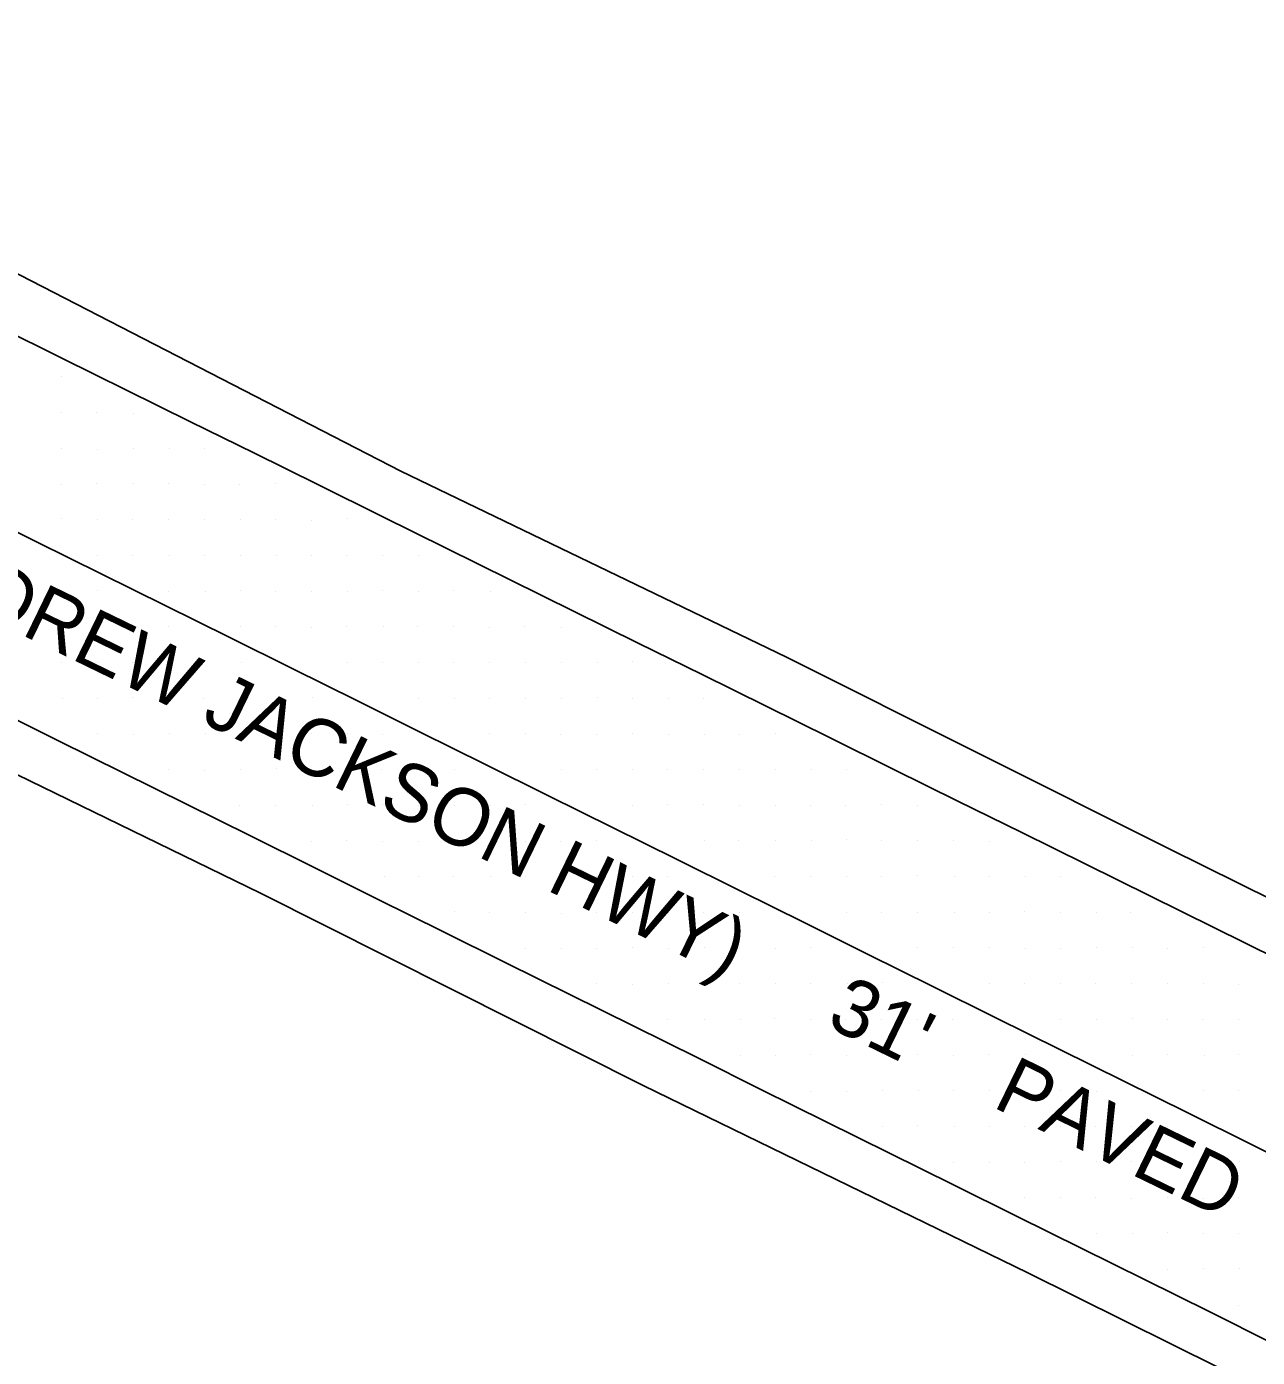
# Model space of a CAD drawing. Extents: x 2244337 to 2251208, y 199469 to 202984.
# Drawn here: x 2244431.6 to 2244517.9, y 202861.5 to 202954.8 of the extents above; entities that cross this region are included whole.
import ezdxf

# ---------------------------------------------------------------- set-up
doc = ezdxf.new("R2010")
doc.units = 0
for name, color, linetype in [('Exist DTM Scan Elevation Point', 7, 'Continuous'), ('Exist Roads EOP', 7, 'Continuous'), ('Exist Roads EOT', 7, 'Continuous'), ('Exist Roads Text', 7, 'Continuous')]:
    doc.layers.add(name, color=color, linetype=linetype)

msp = doc.modelspace()

# ---------------------------------------------------------------- linework, layer by layer
at = {"layer": 'Exist DTM Scan Elevation Point'}
for p, q in [((2244434.067, 202930.21), (2244434.067, 202930.21)), ((2244434.073, 202927.707), (2244434.073, 202927.707)), ((2244436.537, 202927.747), (2244436.537, 202927.747)), ((2244439.096, 202927.674), (2244439.096, 202927.674)), ((2244434.076, 202925.195), (2244434.076, 202925.195)), ((2244436.591, 202925.154), (2244436.591, 202925.154)), ((2244439.102, 202925.209), (2244439.102, 202925.209)), ((2244441.592, 202925.189), (2244441.592, 202925.189)), ((2244444.103, 202925.219), (2244444.103, 202925.219)), ((2244434.046, 202922.709), (2244434.046, 202922.709)), ((2244436.522, 202922.734), (2244436.522, 202922.734)), ((2244439.092, 202922.714), (2244439.092, 202922.714)), ((2244441.565, 202922.742), (2244441.565, 202922.742)), ((2244449.079, 202922.718), (2244449.079, 202922.718)), ((2244444.102, 202922.683), (2244444.102, 202922.683)), ((2244446.562, 202922.65), (2244446.562, 202922.65)), ((2244434.087, 202920.262), (2244434.087, 202920.262)), ((2244436.59, 202920.211), (2244436.59, 202920.211)), ((2244439.049, 202920.203), (2244439.049, 202920.203)), ((2244441.558, 202920.226), (2244441.558, 202920.226)), ((2244444.089, 202920.198), (2244444.089, 202920.198)), ((2244446.621, 202920.205), (2244446.621, 202920.205)), ((2244449.08, 202920.221), (2244449.08, 202920.221)), ((2244451.584, 202920.187), (2244451.584, 202920.187)), ((2244454.078, 202920.262), (2244454.078, 202920.262)), ((2244436.578, 202917.711), (2244436.578, 202917.711)), ((2244439.065, 202917.689), (2244439.065, 202917.689)), ((2244441.6, 202917.712), (2244441.6, 202917.712)), ((2244444.083, 202917.71), (2244444.083, 202917.71)), ((2244446.567, 202917.73), (2244446.567, 202917.73)), ((2244449.127, 202917.714), (2244449.127, 202917.714)), ((2244451.601, 202917.705), (2244451.601, 202917.705)), ((2244454.058, 202917.686), (2244454.058, 202917.686)), ((2244456.564, 202917.669), (2244456.564, 202917.669)), ((2244459.069, 202917.678), (2244459.069, 202917.678)), ((2244446.589, 202915.251), (2244446.589, 202915.251)), ((2244456.571, 202915.24), (2244456.571, 202915.24)), ((2244461.544, 202915.239), (2244461.544, 202915.239)), ((2244431.616, 202915.211), (2244431.616, 202915.211)), ((2244434.1, 202915.221), (2244434.1, 202915.221)), ((2244436.568, 202915.227), (2244436.568, 202915.227)), ((2244441.57, 202915.212), (2244441.57, 202915.212)), ((2244444.114, 202915.195), (2244444.114, 202915.195)), ((2244449.067, 202915.169), (2244449.067, 202915.169)), ((2244451.611, 202915.21), (2244451.611, 202915.21)), ((2244454.108, 202915.187), (2244454.108, 202915.187)), ((2244459.054, 202915.195), (2244459.054, 202915.195)), ((2244464.095, 202915.21), (2244464.095, 202915.21)), ((2244434.13, 202912.716), (2244434.13, 202912.716)), ((2244436.572, 202912.749), (2244436.572, 202912.749)), ((2244439.017, 202912.757), (2244439.017, 202912.757)), ((2244441.578, 202912.747), (2244441.578, 202912.747)), ((2244446.585, 202912.714), (2244446.585, 202912.714)), ((2244449.072, 202912.701), (2244449.072, 202912.701)), ((2244451.575, 202912.664), (2244451.575, 202912.664)), ((2244454.059, 202912.72), (2244454.059, 202912.72)), ((2244456.596, 202912.7), (2244456.596, 202912.7)), ((2244459.035, 202912.76), (2244459.035, 202912.76)), ((2244461.563, 202912.745), (2244461.563, 202912.745)), ((2244464.063, 202912.686), (2244464.063, 202912.686)), ((2244466.532, 202912.713), (2244466.532, 202912.713)), ((2244469.084, 202912.685), (2244469.084, 202912.685)), ((2244434.088, 202910.189), (2244434.088, 202910.189)), ((2244436.58, 202910.226), (2244436.58, 202910.226)), ((2244439.043, 202910.195), (2244439.043, 202910.195)), ((2244441.571, 202910.17), (2244441.571, 202910.17)), ((2244444.039, 202910.231), (2244444.039, 202910.231)), ((2244446.648, 202910.216), (2244446.648, 202910.216)), ((2244454.076, 202910.206), (2244454.076, 202910.206)), ((2244456.57, 202910.231), (2244456.57, 202910.231)), ((2244459.075, 202910.223), (2244459.075, 202910.223)), ((2244461.562, 202910.191), (2244461.562, 202910.191)), ((2244464.068, 202910.207), (2244464.068, 202910.207)), ((2244466.582, 202910.234), (2244466.582, 202910.234)), ((2244469.11, 202910.212), (2244469.11, 202910.212)), ((2244471.593, 202910.221), (2244471.593, 202910.221)), ((2244474.091, 202910.248), (2244474.091, 202910.248)), ((2244434.1, 202907.679), (2244434.1, 202907.679)), ((2244436.576, 202907.719), (2244436.576, 202907.719)), ((2244439.053, 202907.726), (2244439.053, 202907.726)), ((2244441.579, 202907.724), (2244441.579, 202907.724)), ((2244444.012, 202907.712), (2244444.012, 202907.712)), ((2244446.565, 202907.706), (2244446.565, 202907.706)), ((2244449.128, 202907.718), (2244449.128, 202907.718)), ((2244451.622, 202907.74), (2244451.622, 202907.74)), ((2244459.077, 202907.689), (2244459.077, 202907.689)), ((2244461.596, 202907.697), (2244461.596, 202907.697)), ((2244464.069, 202907.697), (2244464.069, 202907.697)), ((2244466.553, 202907.692), (2244466.553, 202907.692)), ((2244469.113, 202907.679), (2244469.113, 202907.679)), ((2244471.598, 202907.726), (2244471.598, 202907.726)), ((2244474.049, 202907.701), (2244474.049, 202907.701)), ((2244476.564, 202907.704), (2244476.564, 202907.704)), ((2244479.053, 202907.695), (2244479.053, 202907.695)), ((2244436.612, 202905.21), (2244436.612, 202905.21)), ((2244439.09, 202905.175), (2244439.09, 202905.175)), ((2244441.592, 202905.231), (2244441.592, 202905.231)), ((2244444.136, 202905.26), (2244444.136, 202905.26)), ((2244446.541, 202905.217), (2244446.541, 202905.217)), ((2244449.067, 202905.185), (2244449.067, 202905.185)), ((2244451.571, 202905.243), (2244451.571, 202905.243)), ((2244454.08, 202905.206), (2244454.08, 202905.206)), ((2244456.531, 202905.197), (2244456.531, 202905.197)), ((2244464.069, 202905.23), (2244464.069, 202905.23)), ((2244466.577, 202905.22), (2244466.577, 202905.22)), ((2244469.062, 202905.191), (2244469.062, 202905.191)), ((2244471.55, 202905.182), (2244471.55, 202905.182)), ((2244474.07, 202905.213), (2244474.07, 202905.213)), ((2244476.576, 202905.184), (2244476.576, 202905.184)), ((2244479.1, 202905.156), (2244479.1, 202905.156)), ((2244481.565, 202905.187), (2244481.565, 202905.187)), ((2244484.063, 202905.207), (2244484.063, 202905.207)), ((2244441.562, 202902.712), (2244441.562, 202902.712)), ((2244444.093, 202902.673), (2244444.093, 202902.673)), ((2244446.581, 202902.705), (2244446.581, 202902.705)), ((2244449.089, 202902.748), (2244449.089, 202902.748)), ((2244451.603, 202902.679), (2244451.603, 202902.679)), ((2244454.04, 202902.714), (2244454.04, 202902.714)), ((2244456.493, 202902.736), (2244456.493, 202902.736)), ((2244459.076, 202902.712), (2244459.076, 202902.712)), ((2244461.592, 202902.706), (2244461.592, 202902.706)), ((2244469.111, 202902.706), (2244469.111, 202902.706)), ((2244471.566, 202902.685), (2244471.566, 202902.685)), ((2244474.085, 202902.7), (2244474.085, 202902.7)), ((2244476.552, 202902.713), (2244476.552, 202902.713)), ((2244479.051, 202902.703), (2244479.051, 202902.703)), ((2244481.595, 202902.703), (2244481.595, 202902.703)), ((2244484.092, 202902.688), (2244484.092, 202902.688)), ((2244486.599, 202902.69), (2244486.599, 202902.69)), ((2244489.09, 202902.689), (2244489.09, 202902.689)), ((2244446.556, 202900.193), (2244446.556, 202900.193)), ((2244449.047, 202900.196), (2244449.047, 202900.196)), ((2244451.626, 202900.198), (2244451.626, 202900.198)), ((2244454.088, 202900.283), (2244454.088, 202900.283)), ((2244456.57, 202900.242), (2244456.57, 202900.242)), ((2244459.05, 202900.207), (2244459.05, 202900.207)), ((2244461.593, 202900.208), (2244461.593, 202900.208)), ((2244464.115, 202900.192), (2244464.115, 202900.192)), ((2244466.587, 202900.251), (2244466.587, 202900.251)), ((2244474.06, 202900.218), (2244474.06, 202900.218)), ((2244476.56, 202900.262), (2244476.56, 202900.262)), ((2244479.051, 202900.246), (2244479.051, 202900.246)), ((2244481.588, 202900.181), (2244481.588, 202900.181)), ((2244484.085, 202900.194), (2244484.085, 202900.194)), ((2244486.552, 202900.2), (2244486.552, 202900.2)), ((2244489.024, 202900.212), (2244489.024, 202900.212)), ((2244491.502, 202900.261), (2244491.502, 202900.261)), ((2244494.056, 202900.212), (2244494.056, 202900.212)), ((2244451.555, 202897.69), (2244451.555, 202897.69)), ((2244454.048, 202897.736), (2244454.048, 202897.736)), ((2244456.567, 202897.682), (2244456.567, 202897.682)), ((2244459.047, 202897.699), (2244459.047, 202897.699)), ((2244461.56, 202897.706), (2244461.56, 202897.706)), ((2244464.134, 202897.714), (2244464.134, 202897.714)), ((2244466.588, 202897.674), (2244466.588, 202897.674)), ((2244469.057, 202897.695), (2244469.057, 202897.695)), ((2244471.544, 202897.735), (2244471.544, 202897.735)), ((2244479.096, 202897.725), (2244479.096, 202897.725)), ((2244481.532, 202897.711), (2244481.532, 202897.711)), ((2244484.12, 202897.731), (2244484.12, 202897.731)), ((2244486.608, 202897.73), (2244486.608, 202897.73)), ((2244489.058, 202897.774), (2244489.058, 202897.774)), ((2244491.529, 202897.72), (2244491.529, 202897.72)), ((2244494.057, 202897.734), (2244494.057, 202897.734)), ((2244496.54, 202897.725), (2244496.54, 202897.725)), ((2244499.125, 202897.694), (2244499.125, 202897.694)), ((2244456.679, 202895.194), (2244456.679, 202895.194)), ((2244459.058, 202895.198), (2244459.058, 202895.198)), ((2244461.53, 202895.21), (2244461.53, 202895.21)), ((2244464.113, 202895.241), (2244464.113, 202895.241)), ((2244466.577, 202895.219), (2244466.577, 202895.219)), ((2244469.016, 202895.206), (2244469.016, 202895.206)), ((2244471.586, 202895.194), (2244471.586, 202895.194)), ((2244474.081, 202895.21), (2244474.081, 202895.21)), ((2244476.545, 202895.182), (2244476.545, 202895.182)), ((2244484.049, 202895.227), (2244484.049, 202895.227)), ((2244486.581, 202895.231), (2244486.581, 202895.231)), ((2244489.098, 202895.235), (2244489.098, 202895.235)), ((2244491.514, 202895.199), (2244491.514, 202895.199)), ((2244494.069, 202895.265), (2244494.069, 202895.265)), ((2244496.615, 202895.225), (2244496.615, 202895.225)), ((2244499.099, 202895.182), (2244499.099, 202895.182)), ((2244501.619, 202895.21), (2244501.619, 202895.21)), ((2244504.038, 202895.191), (2244504.038, 202895.191)), ((2244461.569, 202892.751), (2244461.569, 202892.751)), ((2244464.082, 202892.682), (2244464.082, 202892.682)), ((2244466.573, 202892.719), (2244466.573, 202892.719)), ((2244469.098, 202892.641), (2244469.098, 202892.641)), ((2244471.576, 202892.659), (2244471.576, 202892.659)), ((2244474.07, 202892.689), (2244474.07, 202892.689)), ((2244476.589, 202892.714), (2244476.589, 202892.714)), ((2244479.047, 202892.714), (2244479.047, 202892.714)), ((2244481.588, 202892.723), (2244481.588, 202892.723)), ((2244489.106, 202892.677), (2244489.106, 202892.677)), ((2244491.562, 202892.713), (2244491.562, 202892.713)), ((2244494.049, 202892.719), (2244494.049, 202892.719)), ((2244496.628, 202892.716), (2244496.628, 202892.716)), ((2244499.116, 202892.699), (2244499.116, 202892.699)), ((2244501.584, 202892.772), (2244501.584, 202892.772)), ((2244504.066, 202892.708), (2244504.066, 202892.708)), ((2244506.578, 202892.699), (2244506.578, 202892.699)), ((2244509.013, 202892.711), (2244509.013, 202892.711)), ((2244466.6, 202890.187), (2244466.6, 202890.187)), ((2244469.068, 202890.188), (2244469.068, 202890.188)), ((2244471.559, 202890.172), (2244471.559, 202890.172)), ((2244474.084, 202890.248), (2244474.084, 202890.248)), ((2244476.58, 202890.194), (2244476.58, 202890.194)), ((2244479.102, 202890.209), (2244479.102, 202890.209)), ((2244481.596, 202890.244), (2244481.596, 202890.244)), ((2244484.11, 202890.192), (2244484.11, 202890.192)), ((2244486.568, 202890.214), (2244486.568, 202890.214)), ((2244494.026, 202890.224), (2244494.026, 202890.224)), ((2244496.565, 202890.206), (2244496.565, 202890.206)), ((2244499.084, 202890.213), (2244499.084, 202890.213)), ((2244501.619, 202890.185), (2244501.619, 202890.185)), ((2244504.072, 202890.138), (2244504.072, 202890.138)), ((2244506.563, 202890.225), (2244506.563, 202890.225)), ((2244509.098, 202890.213), (2244509.098, 202890.213)), ((2244511.605, 202890.182), (2244511.605, 202890.182)), ((2244514.088, 202890.228), (2244514.088, 202890.228)), ((2244471.563, 202887.736), (2244471.563, 202887.736)), ((2244474.089, 202887.678), (2244474.089, 202887.678)), ((2244476.59, 202887.706), (2244476.59, 202887.706)), ((2244479.05, 202887.722), (2244479.05, 202887.722)), ((2244481.556, 202887.69), (2244481.556, 202887.69)), ((2244484.108, 202887.689), (2244484.108, 202887.689)), ((2244486.549, 202887.733), (2244486.549, 202887.733)), ((2244489.134, 202887.727), (2244489.134, 202887.727)), ((2244491.58, 202887.758), (2244491.58, 202887.758)), ((2244499.097, 202887.703), (2244499.097, 202887.703)), ((2244501.535, 202887.694), (2244501.535, 202887.694)), ((2244504.054, 202887.723), (2244504.054, 202887.723)), ((2244506.559, 202887.73), (2244506.559, 202887.73)), ((2244509.073, 202887.726), (2244509.073, 202887.726)), ((2244511.576, 202887.739), (2244511.576, 202887.739)), ((2244514.072, 202887.731), (2244514.072, 202887.731)), ((2244516.569, 202887.659), (2244516.569, 202887.659)), ((2244476.531, 202885.19), (2244476.531, 202885.19)), ((2244479.093, 202885.227), (2244479.093, 202885.227)), ((2244481.631, 202885.211), (2244481.631, 202885.211)), ((2244484.061, 202885.248), (2244484.061, 202885.248)), ((2244486.552, 202885.214), (2244486.552, 202885.214)), ((2244489.036, 202885.201), (2244489.036, 202885.201)), ((2244491.546, 202885.225), (2244491.546, 202885.225)), ((2244494.084, 202885.193), (2244494.084, 202885.193)), ((2244496.511, 202885.211), (2244496.511, 202885.211)), ((2244504.1, 202885.205), (2244504.1, 202885.205)), ((2244506.571, 202885.221), (2244506.571, 202885.221)), ((2244509.098, 202885.238), (2244509.098, 202885.238)), ((2244511.56, 202885.172), (2244511.56, 202885.172)), ((2244514.059, 202885.193), (2244514.059, 202885.193)), ((2244516.556, 202885.186), (2244516.556, 202885.186)), ((2244481.621, 202882.692), (2244481.621, 202882.692)), ((2244484.075, 202882.698), (2244484.075, 202882.698)), ((2244486.583, 202882.723), (2244486.583, 202882.723)), ((2244489.048, 202882.689), (2244489.048, 202882.689)), ((2244491.594, 202882.715), (2244491.594, 202882.715)), ((2244494.081, 202882.724), (2244494.081, 202882.724)), ((2244496.585, 202882.687), (2244496.585, 202882.687)), ((2244499.054, 202882.715), (2244499.054, 202882.715)), ((2244501.607, 202882.713), (2244501.607, 202882.713)), ((2244509.108, 202882.687), (2244509.108, 202882.687)), ((2244511.571, 202882.735), (2244511.571, 202882.735)), ((2244514.149, 202882.701), (2244514.149, 202882.701)), ((2244516.566, 202882.709), (2244516.566, 202882.709)), ((2244486.554, 202880.155), (2244486.554, 202880.155)), ((2244489.047, 202880.177), (2244489.047, 202880.177)), ((2244491.588, 202880.206), (2244491.588, 202880.206)), ((2244494.124, 202880.211), (2244494.124, 202880.211)), ((2244496.559, 202880.223), (2244496.559, 202880.223)), ((2244499.087, 202880.226), (2244499.087, 202880.226)), ((2244501.593, 202880.207), (2244501.593, 202880.207)), ((2244504.095, 202880.207), (2244504.095, 202880.207)), ((2244506.585, 202880.162), (2244506.585, 202880.162)), ((2244514.119, 202880.229), (2244514.119, 202880.229)), ((2244516.563, 202880.239), (2244516.563, 202880.239)), ((2244491.566, 202877.667), (2244491.566, 202877.667)), ((2244494.081, 202877.738), (2244494.081, 202877.738)), ((2244496.612, 202877.719), (2244496.612, 202877.719)), ((2244499.082, 202877.669), (2244499.082, 202877.669)), ((2244501.521, 202877.682), (2244501.521, 202877.682)), ((2244504.077, 202877.694), (2244504.077, 202877.694)), ((2244506.55, 202877.729), (2244506.55, 202877.729)), ((2244509.064, 202877.72), (2244509.064, 202877.72)), ((2244511.553, 202877.725), (2244511.553, 202877.725)), ((2244496.574, 202875.194), (2244496.574, 202875.194)), ((2244499.066, 202875.208), (2244499.066, 202875.208)), ((2244501.565, 202875.201), (2244501.565, 202875.201)), ((2244504.065, 202875.213), (2244504.065, 202875.213)), ((2244506.581, 202875.222), (2244506.581, 202875.222)), ((2244509.084, 202875.264), (2244509.084, 202875.264)), ((2244511.549, 202875.195), (2244511.549, 202875.195)), ((2244514.081, 202875.187), (2244514.081, 202875.187)), ((2244516.613, 202875.221), (2244516.613, 202875.221)), ((2244501.567, 202872.742), (2244501.567, 202872.742)), ((2244504.087, 202872.716), (2244504.087, 202872.716)), ((2244506.535, 202872.714), (2244506.535, 202872.714)), ((2244509.084, 202872.668), (2244509.084, 202872.668)), ((2244511.565, 202872.717), (2244511.565, 202872.717)), ((2244514.085, 202872.686), (2244514.085, 202872.686)), ((2244516.56, 202872.708), (2244516.56, 202872.708)), ((2244506.565, 202870.209), (2244506.565, 202870.209)), ((2244509.103, 202870.208), (2244509.103, 202870.208)), ((2244511.573, 202870.241), (2244511.573, 202870.241)), ((2244514.063, 202870.199), (2244514.063, 202870.199)), ((2244516.574, 202870.209), (2244516.574, 202870.209)), ((2244511.545, 202867.704), (2244511.545, 202867.704)), ((2244514.113, 202867.749), (2244514.113, 202867.749)), ((2244516.595, 202867.722), (2244516.595, 202867.722)), ((2244516.566, 202865.169), (2244516.566, 202865.169))]:
    msp.add_line(p, q, dxfattribs=at)
at = {"layer": 'Exist Roads EOP'}
for points in [[(2244395.66, 202954.756), (2244404.184, 202950.471), (2244431.163, 202937.333), (2244457.845, 202923.616), (2244484.862, 202910.572), (2244511.697, 202897.153), (2244538.582, 202883.845), (2244565.542, 202870.685), (2244592.439, 202857.393), (2244619.277, 202843.98), (2244646.192, 202830.724), (2244673.008, 202817.264), (2244699.795, 202803.753), (2244726.705, 202790.508), (2244753.635, 202777.293), (2244780.493, 202763.918), (2244807.359, 202750.564), (2244834.191, 202737.171), (2244861.067, 202723.837), (2244887.943, 202710.51), (2244914.918, 202697.381), (2244941.727, 202683.916)], [(2244958.852, 202641.188), (2244931.978, 202654.521), (2244905.101, 202667.849), (2244878.239, 202681.207), (2244851.363, 202694.532), (2244824.429, 202707.745), (2244797.543, 202721.054), (2244770.648, 202734.347), (2244743.765, 202747.663), (2244716.885, 202760.99), (2244690.176, 202774.662), (2244663.014, 202787.416), (2244636.151, 202800.759), (2244609.262, 202814.042), (2244582.345, 202827.294), (2244555.462, 202840.633), (2244528.659, 202854.109), (2244501.785, 202867.438), (2244474.812, 202880.574), (2244448.01, 202894.052), (2244421.028, 202907.168), (2244394.334, 202920.84), (2244380.975, 202927.4)]]:
    msp.add_lwpolyline(points, dxfattribs=at)
at = {"layer": 'Exist Roads EOT'}
for points in [[(2244429.645, 202933.723), (2244434.129, 202931.51), (2244438.611, 202929.294), (2244443.093, 202927.077), (2244447.574, 202924.861), (2244452.056, 202922.645), (2244456.539, 202920.429), (2244461.021, 202918.214), (2244465.504, 202916), (2244469.987, 202913.785), (2244474.47, 202911.571), (2244478.953, 202909.357), (2244483.436, 202907.142), (2244487.919, 202904.928), (2244492.402, 202902.714), (2244496.885, 202900.499), (2244501.368, 202898.285), (2244505.85, 202896.07), (2244510.332, 202893.854), (2244514.814, 202891.637), (2244519.295, 202889.419)], [(2244427.876, 202920.857), (2244432.356, 202918.637), (2244436.836, 202916.417), (2244441.317, 202914.197), (2244445.797, 202911.978), (2244450.277, 202909.757), (2244454.756, 202907.536), (2244459.236, 202905.314), (2244463.715, 202903.092), (2244468.194, 202900.87), (2244472.673, 202898.648), (2244477.152, 202896.426), (2244481.631, 202894.204), (2244486.11, 202891.981), (2244490.588, 202889.758), (2244495.067, 202887.535), (2244499.546, 202885.312), (2244504.025, 202883.091), (2244508.505, 202880.87), (2244512.986, 202878.651), (2244517.467, 202876.432), (2244521.947, 202874.214)], [(2244518.961, 202862.507), (2244514.481, 202864.729), (2244510.002, 202866.95), (2244505.522, 202869.171), (2244501.043, 202871.393), (2244496.564, 202873.614), (2244492.084, 202875.836), (2244487.605, 202878.058), (2244483.126, 202880.279), (2244478.646, 202882.501), (2244474.167, 202884.723), (2244469.688, 202886.945), (2244465.209, 202889.167), (2244460.73, 202891.389), (2244456.251, 202893.611), (2244451.771, 202895.833), (2244447.292, 202898.055), (2244442.813, 202900.277), (2244438.334, 202902.499), (2244433.854, 202904.72), (2244429.375, 202906.942)]]:
    msp.add_lwpolyline(points, dxfattribs=at)

# ---------------------------------------------------------------- texts
at = {"layer": 'Exist Roads Text'}
msp.add_text("US 74 WEST  (ANDREW JACKSON HWY)     31'    PAVED", height=4.02, rotation=334.07572, dxfattribs=at).set_placement((2244387.888, 202933.226))

doc.saveas('drawing.dxf')
